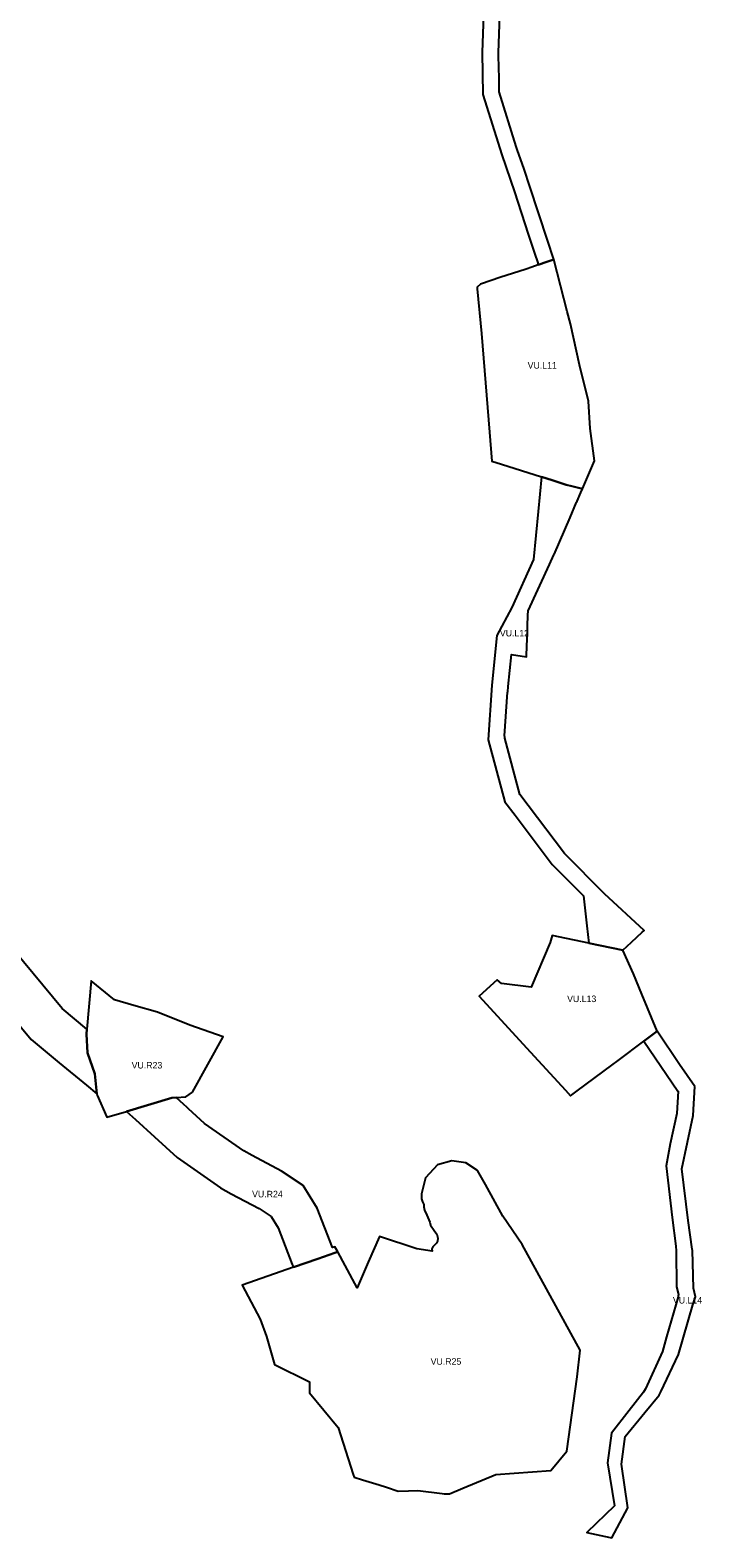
# Model space of a CAD drawing. Extents: x -439083 to -433688, y -1130252 to -1121189.
# Drawn here: x -434920 to -433688, y -1130252 to -1127489 of the extents above; entities that cross this region are included whole.
import ezdxf

# ---------------------------------------------------------------- set-up
doc = ezdxf.new("R2010")
doc.units = 0
doc.layers.add('Vrstva 28', color=7, linetype='Continuous')
doc.layers.add('Vrstva 31', color=7, linetype='Continuous')

msp = doc.modelspace()

# ---------------------------------------------------------------- linework, layer by layer
at = {"layer": 'Vrstva 28'}
for p, q in [((-433987.8, -1127918.9), (-433972.2, -1127913.4)), ((-433972.2, -1127913.4), (-433987.8, -1127918.9)), ((-433972.2, -1127913.4), (-433961.4, -1127909.6)), ((-433961.4, -1127909.6), (-433972.2, -1127913.4)), ((-433959.4, -1127908.9), (-433961.4, -1127909.6)), ((-433934.7, -1128004.5), (-433959.4, -1127908.9)), ((-433962.5, -1128313.8), (-433982.2, -1128307.6)), ((-433936.5, -1128322.1), (-433962.5, -1128313.8)), ((-433907, -1128329.4), (-433908.1, -1128329.1)), ((-433908.1, -1128329.1), (-433907, -1128329.4)), ((-434063.9, -1128598.6), (-434073.1, -1128689.1)), ((-433832.7, -1129174.8), (-433895.3, -1129161.9)), ((-433895.3, -1129161.9), (-433832.7, -1129174.8)), ((-433769.9, -1129323.7), (-433797.9, -1129255.7)), ((-434816.2, -1129328.8), (-434815.5, -1129319.6)), ((-434814.8, -1129363.2), (-434816.2, -1129328.8)), ((-433794, -1129341.7), (-433769.9, -1129323.7)), ((-433769.9, -1129323.7), (-433794, -1129341.7)), ((-434801, -1129401.8), (-434814.8, -1129363.2)), ((-434814.8, -1129363.2), (-434801, -1129401.8)), ((-434797.4, -1129438.3), (-434801, -1129401.8)), ((-434801, -1129401.8), (-434797.4, -1129438.3)), ((-434633.9, -1129443.9), (-434622, -1129435.3)), ((-433703.9, -1129478.2), (-433700.9, -1129425)), ((-434660.1, -1129445.8), (-434742.9, -1129470.6)), ((-434742.9, -1129470.6), (-434660.1, -1129445.8)), ((-434651.9, -1129445.2), (-434660.1, -1129445.8)), ((-434391.9, -1129740.6), (-434436.8, -1129756.2)), ((-434436.8, -1129756.2), (-434391.9, -1129740.6)), ((-434361.2, -1129729.9), (-434391.9, -1129740.6)), ((-434391.9, -1129740.6), (-434361.2, -1129729.9)), ((-434355.7, -1129727.9), (-434361.2, -1129729.9))]:
    msp.add_line(p, q, dxfattribs=at)
for points in [[(-434842.7, -1127132.6), (-434833.1, -1127156.7), (-434788.7, -1127272.9), (-434608.5, -1127247.6), (-434591.4, -1127283.7), (-434446.6, -1127267.3), (-434321.7, -1127253.2), (-434245.1, -1127244.3), (-434172.3, -1127239.5), (-434137, -1127237.6), (-434124.4, -1127236.5), (-434112.6, -1127250.3), (-434081.6, -1127332.1), (-434087.1, -1127425.4), (-434090.7, -1127529.7), (-434089.3, -1127606.6), (-434054.8, -1127717.1), (-434031.6, -1127785), (-434006.2, -1127862.5), (-433994.2, -1127899.2), (-433989.5, -1127913.4), (-433988.2, -1127917.4), (-433987.8, -1127918.9)], [(-433961.4, -1127909.6), (-433959.4, -1127908.9), (-433970.9, -1127873.8), (-434003.1, -1127775.5), (-434014, -1127743.8), (-434026.3, -1127707.8), (-434028.1, -1127702.1), (-434059.4, -1127601.7), (-434059.8, -1127577.4), (-434060.5, -1127536.1), (-434060.6, -1127529.9), (-434057.2, -1127428)], [(-433987.8, -1127918.9), (-433999.4, -1127923), (-434010.2, -1127926.8), (-434058.6, -1127942.2), (-434074.4, -1127947.4), (-434093.6, -1127954.4), (-434100, -1127959.7), (-434099.7, -1127963), (-434091.7, -1128044.9), (-434077.2, -1128225.8), (-434073, -1128278.7), (-434055.5, -1128284.2), (-433982.2, -1128307.6), (-433962.5, -1128313.8), (-433936.5, -1128322.1), (-433926.3, -1128324.6)], [(-433907, -1128329.4), (-433884.9, -1128278), (-433892.4, -1128218.8), (-433895.6, -1128169.1), (-433912.3, -1128102.5), (-433928.9, -1128026.9), (-433934.7, -1128004.5)], [(-433982.2, -1128307.6), (-433988.2, -1128371.2), (-433996.4, -1128459.3), (-434036.2, -1128546.8), (-434063.9, -1128598.6)], [(-433832.7, -1129174.8), (-433817.1, -1129160.5), (-433797.2, -1129142.2), (-433793.5, -1129138.8), (-433866.2, -1129072), (-433939.7, -1128998.1), (-434006.4, -1128909.9), (-434021.4, -1128890), (-434049.3, -1128786.4), (-434049.2, -1128784.7), (-434049.9, -1128782.1), (-434044.3, -1128701.9), (-434043.9, -1128701.6), (-434043.2, -1128691.5), (-434037.2, -1128633), (-434009.3, -1128637.2), (-434009.2, -1128634.4), (-434008.2, -1128603.5), (-434007.8, -1128591.9), (-434007.4, -1128582), (-434006.7, -1128560.7), (-434006.5, -1128553.8), (-434006.1, -1128553), (-433967.5, -1128468.3), (-433959.3, -1128450.3), (-433959, -1128449.7), (-433929.6, -1128381.8), (-433917.7, -1128354.2), (-433916.6, -1128351.8), (-433909.8, -1128336), (-433907, -1128329.4)], [(-433908.1, -1128329.1), (-433911.5, -1128328.2), (-433926.3, -1128324.6), (-433936.5, -1128322.1)], [(-433926.3, -1128324.6), (-433911.5, -1128328.2), (-433908.1, -1128329.1)], [(-434073.1, -1128689.1), (-434079.6, -1128789.4), (-434048.9, -1128903.4), (-434030.3, -1128927.9), (-433962.4, -1129017.8), (-433905, -1129075.6), (-433898.8, -1129130.6), (-433895.3, -1129161.9)], [(-434815.5, -1129319.6), (-434861, -1129282.1), (-435095.1, -1129000.3), (-435143.5, -1128938.4)], [(-435181.5, -1129019.6), (-435157.3, -1129050.5), (-434917.7, -1129339), (-434866.4, -1129381.3), (-434816.5, -1129422.6), (-434797.4, -1129438.3)], [(-433895.3, -1129161.9), (-433962.5, -1129148), (-433966, -1129161), (-434001.1, -1129242.6), (-434055.1, -1129235.9), (-434063.4, -1129229.2), (-434096.4, -1129259.6), (-434009.5, -1129354.1), (-433938.2, -1129431.6), (-433928.7, -1129441.9), (-433916.3, -1129432.7), (-433853.2, -1129385.7), (-433841.6, -1129377.1), (-433794, -1129341.7)], [(-433797.9, -1129255.7), (-433813.1, -1129218.7), (-433832.7, -1129174.8)], [(-434622, -1129435.3), (-434565.6, -1129334.1), (-434626.7, -1129312.6), (-434685.9, -1129288.7), (-434729.4, -1129276.3), (-434765.2, -1129265.8), (-434808.1, -1129231.4), (-434815.5, -1129319.6)], [(-434815.5, -1129319.6), (-434816.2, -1129328.8), (-434814.8, -1129363.2)], [(-433700.9, -1129425), (-433728.7, -1129384.3), (-433769.9, -1129323.7)], [(-433794, -1129341.7), (-433731.6, -1129433.2), (-433731.4, -1129433.5), (-433733.7, -1129474.2), (-433745.7, -1129530.3), (-433753.5, -1129570.3), (-433742.2, -1129665.3), (-433735.8, -1129717.4), (-433735, -1129726.3), (-433734.6, -1129792.3), (-433730.6, -1129806.2), (-433731.4, -1129809.3), (-433731.1, -1129810.5), (-433752.4, -1129883.7), (-433760, -1129910.7), (-433791.5, -1129978.8), (-433794.9, -1129985.4), (-433821.1, -1130018.6), (-433853.6, -1130060.5), (-433860.7, -1130114.4), (-433848.3, -1130193.2), (-433898.9, -1130242.4), (-433856.1, -1130251.5), (-433853, -1130252.2), (-433823.8, -1130197.1), (-433835.5, -1130117.3), (-433828.6, -1130066.3), (-433792.2, -1130022.3), (-433766.2, -1129990.7), (-433763.3, -1129984.8), (-433730.5, -1129915.9), (-433704.1, -1129825.2), (-433699.8, -1129810.4), (-433703.4, -1129794.8), (-433705.3, -1129725.8), (-433705.7, -1129722.8), (-433713, -1129670.4), (-433724.7, -1129575.7), (-433703.9, -1129478.2)], [(-434797.4, -1129438.3), (-434797.1, -1129441), (-434779.3, -1129481.2), (-434774.7, -1129480.1), (-434742.9, -1129470.6)], [(-434660.1, -1129445.8), (-434651.9, -1129445.2), (-434633.9, -1129443.9)], [(-434361.2, -1129729.9), (-434355.7, -1129727.9), (-434360.8, -1129718.5), (-434365, -1129720.3), (-434393.3, -1129648.1), (-434419.1, -1129606.6), (-434458.7, -1129579.9), (-434512.7, -1129551.3), (-434527.9, -1129542.7), (-434600, -1129492.5), (-434629.3, -1129465.9), (-434632.5, -1129462.9), (-434637.7, -1129458.2), (-434651.9, -1129445.2)], [(-434742.9, -1129470.6), (-434731.9, -1129480.5), (-434726.6, -1129485.4), (-434691.6, -1129517.3), (-434650, -1129555.2), (-434570.5, -1129610.5), (-434551, -1129621.5), (-434500, -1129648.6), (-434478, -1129663.4), (-434465.1, -1129684.2), (-434438.9, -1129750.9), (-434436.8, -1129756.2)], [(-434497.9, -1129851.3), (-434486, -1129883), (-434471.5, -1129934.6), (-434407.3, -1129966.1), (-434407.3, -1129986.6), (-434355.1, -1130050.1), (-434327.1, -1130135.9), (-434325.4, -1130141.1), (-434310, -1130145.8), (-434279.8, -1130154.9), (-434266.2, -1130159.5), (-434245, -1130166.6), (-434226, -1130165.9), (-434209, -1130165.3), (-434164.1, -1130171), (-434160.7, -1130171.3), (-434156.2, -1130171.5), (-434150.7, -1130171.7), (-434126.5, -1130161.3), (-434065.8, -1130135.9), (-433965.1, -1130128.5), (-433935.2, -1130093), (-433916.6, -1129956.8), (-433911, -1129908.3), (-434017.3, -1129714.2), (-434052.6, -1129662.8), (-434084.7, -1129604.6), (-434099.6, -1129578.6), (-434120.6, -1129565), (-434146.6, -1129561.3), (-434172.6, -1129568.7), (-434194.9, -1129592.3), (-434202.2, -1129621.4), (-434201.8, -1129626.7), (-434201.8, -1129631), (-434200.2, -1129636.4), (-434197.5, -1129641), (-434197.5, -1129645.5), (-434196.6, -1129651.5), (-434192.4, -1129660.7), (-434186.8, -1129673.5), (-434185.3, -1129679.1), (-434179, -1129688.8), (-434174.1, -1129695.7), (-434172.2, -1129702.7), (-434172.8, -1129708.3), (-434174.4, -1129712.2), (-434178.4, -1129715.9), (-434181.5, -1129718.7), (-434183.1, -1129722.6), (-434182.5, -1129726.7), (-434210.3, -1129722.7), (-434279.1, -1129700), (-434299.6, -1129747.1), (-434320, -1129794.1), (-434342.2, -1129753.1), (-434355.7, -1129727.9)], [(-434436.8, -1129756.2), (-434531, -1129789.1), (-434497.9, -1129851.3)]]:
    msp.add_lwpolyline(points, dxfattribs=at)

# ---------------------------------------------------------------- texts
at = {"layer": 'Vrstva 31'}
for s, p in [('VU.L11', (-434007.3, -1128109.1)), ('VU.L12', (-434058.3, -1128600)), ('VU.L13', (-433934.9, -1129270.2)), ('VU.R23', (-434733.6, -1129391.9)), ('VU.R24', (-434512.7, -1129628.1)), ('VU.L14', (-433740.9, -1129822.7)), ('VU.R25', (-434185.2, -1129934.9))]:
    msp.add_text(s, height=12, dxfattribs=at).set_placement(p)

doc.saveas('drawing.dxf')
